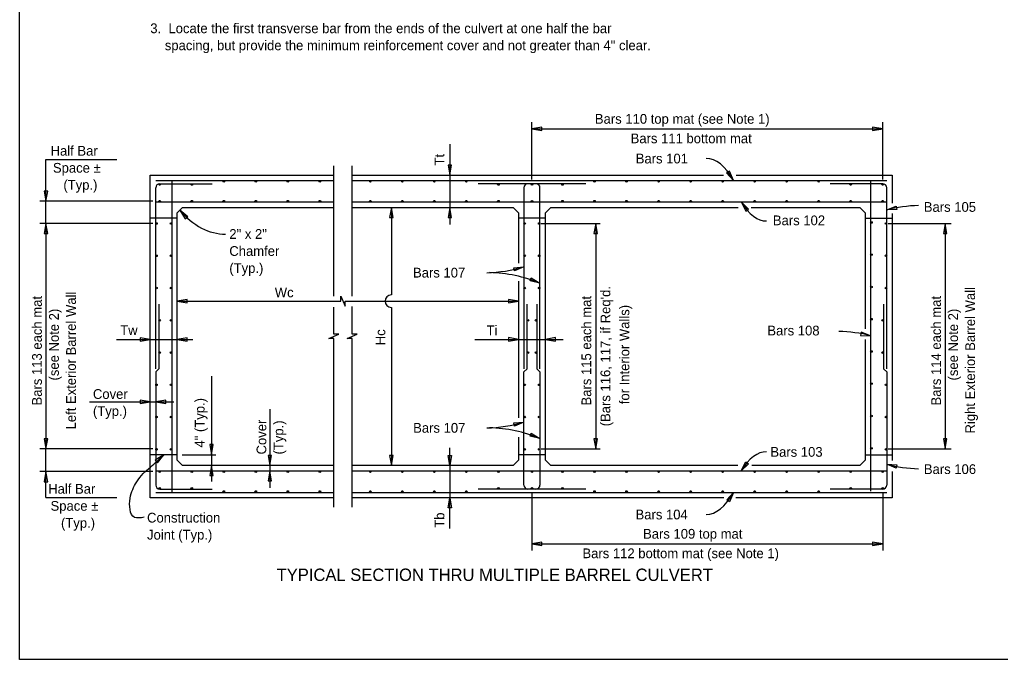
# Model space of a CAD drawing. Extents: x -178 to 179, y -5 to 45.
# Drawn here: x 2.47 to 32.88, y 3.35 to 23.18 of the extents above; entities that cross this region are included whole.
import ezdxf

# ---------------------------------------------------------------- set-up
doc = ezdxf.new("R2010")
doc.units = 0
for name, color, linetype in [('AdhocPoint_dp', 7, 'Continuous'), ('Leader', 7, 'Continuous'), ('PlotBorder_dp', 7, 'Continuous'), ('Rebar', 7, 'Continuous'), ('StrMiscConc', 7, 'Continuous'), ('StrMiscConc_h', 7, 'Continuous'), ('Symbols', 7, 'Continuous')]:
    doc.layers.add(name, color=color, linetype=linetype)

msp = doc.modelspace()

# ---------------------------------------------------------------- linework, layer by layer
at = {"layer": 'Leader'}
msp.add_arc((13.998, 14.455), 0.195, 90, 270, dxfattribs=at)
for centre, major_axis, start_param, end_param in [((23.835, 15.12), (0.076, -3.758), 2.52174, 3.141593), ((25.556, 20.698), (0.076, -3.758), 5.70763, 6.283185), ((25.556, 6.027), (0.076, 3.758), 0, 0.575555), ((23.835, 11.605), (0.076, 3.758), 3.141593, 3.761445)]:
    msp.add_ellipse(centre, major_axis=major_axis, ratio=0.38143, start_param=start_param, end_param=end_param, dxfattribs=at)
msp.add_spline([(6.339, 7.756), (6.039, 7.754), (5.902, 8.348), (6.106, 8.85), (6.303, 9.11), (6.531, 9.312), (6.943, 9.696)], degree=3, dxfattribs=at)
at = {"layer": 'PlotBorder_dp'}
for p, q in [((18.356, 18.228), (18.356, 19.999)), ((18.356, 19.793), (29.231, 19.793)), ((29.231, 18.228), (29.231, 19.999)), ((15.812, 19.32), (15.812, 18.362)), ((3.291, 17.554), (3.291, 18.842)), ((3.291, 18.842), (5.485, 18.842)), ((15.812, 18.362), (15.812, 17.362)), ((6.605, 17.554), (3.097, 17.554)), ((3.291, 16.862), (3.291, 17.554)), ((13.998, 17.362), (13.998, 14.651)), ((15.812, 17.362), (15.812, 16.831)), ((6.605, 16.862), (3.097, 16.862)), ((3.291, 16.862), (3.291, 9.88)), ((18.639, 16.862), (20.469, 16.862)), ((20.332, 16.862), (20.332, 9.88)), ((29.4, 16.862), (31.355, 16.862)), ((31.163, 16.862), (31.163, 9.88)), ((13.998, 14.26), (13.998, 9.362)), ((5.481, 13.264), (6.526, 13.264)), ((6.526, 13.264), (7.36, 13.264)), ((7.36, 13.264), (7.843, 13.264)), ((16.582, 13.271), (17.939, 13.271)), ((17.939, 13.271), (18.772, 13.271)), ((18.772, 13.271), (19.324, 13.271)), ((8.423, 12.13), (8.423, 9.696)), ((4.636, 11.336), (6.526, 11.336)), ((6.526, 11.336), (6.693, 11.336)), ((6.693, 11.336), (7.256, 11.336)), ((10.234, 11.103), (10.234, 9.362)), ((6.605, 9.88), (3.097, 9.88)), ((3.291, 9.171), (3.291, 9.88)), ((15.812, 9.362), (15.812, 9.912)), ((18.639, 9.88), (20.469, 9.88)), ((29.4, 9.88), (31.355, 9.88)), ((7.513, 9.696), (8.555, 9.696)), ((8.423, 9.696), (8.423, 9.362)), ((6.605, 9.171), (3.097, 9.171)), ((3.291, 8.367), (3.291, 9.171)), ((8.423, 9.362), (8.423, 8.868)), ((10.234, 9.362), (10.234, 9.196)), ((10.234, 9.196), (10.234, 8.665)), ((15.812, 9.362), (15.812, 8.362)), ((3.291, 8.367), (5.485, 8.367)), ((15.812, 7.405), (15.812, 8.362)), ((18.356, 8.496), (18.356, 6.726)), ((29.231, 8.496), (29.231, 6.726)), ((18.356, 6.932), (29.231, 6.932))]:
    msp.add_line(p, q, dxfattribs=at)
for points in [[(2.474, 42.838), (63.281, 42.838), (63.281, 3.352), (2.474, 3.352)], [(18.356, 19.793), (18.668, 19.74), (18.668, 19.846)], [(29.231, 19.793), (28.918, 19.846), (28.918, 19.74)], [(15.812, 18.362), (15.865, 18.675), (15.76, 18.675)], [(24.606, 18.196), (24.482, 18.487), (24.392, 18.43)], [(3.291, 17.554), (3.344, 17.867), (3.238, 17.867)], [(13.998, 17.362), (13.945, 17.05), (14.051, 17.05)], [(15.812, 17.362), (15.76, 17.05), (15.865, 17.05)], [(24.84, 17.529), (24.983, 17.247), (25.069, 17.31)], [(29.356, 17.282), (29.649, 17.403), (29.672, 17.299)], [(7.443, 17.279), (7.602, 17.005), (7.684, 17.073)], [(3.291, 16.862), (3.238, 16.55), (3.344, 16.55)], [(20.332, 16.862), (20.28, 16.55), (20.385, 16.55)], [(31.163, 16.862), (31.11, 16.55), (31.216, 16.55)], [(18.106, 15.519), (17.816, 15.39), (17.79, 15.493)], [(18.606, 15.01), (18.297, 15.081), (18.337, 15.179)], [(7.36, 14.455), (7.672, 14.403), (7.672, 14.508)], [(17.939, 14.455), (17.627, 14.508), (17.627, 14.403)], [(28.856, 13.382), (28.561, 13.497), (28.539, 13.393)], [(6.526, 13.264), (6.214, 13.317), (6.214, 13.211)], [(7.36, 13.264), (7.672, 13.211), (7.672, 13.317)], [(17.939, 13.271), (17.627, 13.324), (17.627, 13.218)], [(18.772, 13.271), (19.085, 13.218), (19.085, 13.324)], [(6.526, 11.336), (6.214, 11.389), (6.214, 11.283)], [(6.693, 11.336), (7.005, 11.283), (7.005, 11.389)], [(18.106, 10.709), (17.817, 10.579), (17.79, 10.682)], [(18.606, 10.2), (18.297, 10.27), (18.337, 10.368)], [(3.291, 9.88), (3.344, 10.193), (3.238, 10.193)], [(20.332, 9.88), (20.385, 10.193), (20.28, 10.193)], [(31.163, 9.88), (31.216, 10.193), (31.11, 10.193)], [(8.423, 9.696), (8.476, 10.008), (8.37, 10.008)], [(6.943, 9.696), (6.678, 9.522), (6.751, 9.444)], [(10.234, 9.362), (10.287, 9.675), (10.181, 9.675)], [(13.998, 9.362), (14.051, 9.675), (13.945, 9.675)], [(15.812, 9.362), (15.76, 9.675), (15.865, 9.675)], [(24.84, 9.196), (24.982, 9.479), (25.068, 9.416)], [(3.291, 9.171), (3.238, 8.858), (3.344, 8.858)], [(8.423, 9.362), (8.37, 9.05), (8.476, 9.05)], [(10.234, 9.196), (10.181, 8.883), (10.287, 8.883)], [(29.356, 9.398), (29.672, 9.387), (29.651, 9.283)], [(24.606, 8.529), (24.482, 8.238), (24.393, 8.295)], [(15.812, 8.362), (15.865, 8.05), (15.76, 8.05)], [(18.356, 6.932), (18.668, 6.879), (18.668, 6.984)], [(29.231, 6.932), (28.918, 6.984), (28.918, 6.879)]]:
    msp.add_lwpolyline(points, close=True, dxfattribs=at)
for centre, start, end in [((30.431, 13.079), 91.2114, 104.3468), ((16.864, 19.676), 271.2114, 286.6314), ((16.947, 11.001), 67.5277, 88.7886), ((27.781, 9.179), 75.6532, 88.7886), ((16.864, 14.866), 271.2114, 286.6314), ((16.947, 6.191), 67.5277, 88.7886), ((30.431, 13.601), 255.6532, 268.7886)]:
    msp.add_arc(centre, 4.339, start, end, dxfattribs=at)
msp.add_ellipse((8.83, 20.041), major_axis=(-0.03, 3.508), ratio=0.647453, start_param=2.471513, end_param=3.141593, dxfattribs=at)
at = {"layer": 'Rebar'}
for p, q in [((6.693, 18.196), (12.214, 18.196)), ((6.693, 12.362), (6.693, 17.971)), ((6.818, 18.096), (8.443, 18.096)), ((7.193, 18.196), (7.193, 8.529)), ((12.786, 18.196), (29.356, 18.196)), ((18.481, 18.096), (16.689, 18.096)), ((18.106, 17.971), (18.106, 12.362)), ((20.022, 18.096), (18.231, 18.096)), ((18.606, 12.362), (18.606, 17.971)), ((29.231, 18.096), (27.606, 18.096)), ((28.856, 18.196), (28.856, 8.561)), ((29.356, 12.362), (29.356, 17.971)), ((6.693, 17.529), (12.214, 17.529)), ((12.786, 17.529), (29.356, 17.529)), ((6.793, 14.362), (6.793, 12.362)), ((18.206, 12.362), (18.206, 14.362)), ((18.506, 14.362), (18.506, 12.362)), ((29.256, 14.362), (29.256, 12.362)), ((6.793, 12.362), (6.693, 12.262)), ((6.693, 12.262), (6.693, 8.754)), ((18.106, 12.262), (18.206, 12.362)), ((18.106, 8.754), (18.106, 12.262)), ((18.506, 12.362), (18.606, 12.262)), ((18.606, 12.262), (18.606, 8.754)), ((29.256, 12.362), (29.356, 12.262)), ((29.356, 12.262), (29.356, 8.754)), ((6.693, 9.196), (12.214, 9.196)), ((12.786, 9.196), (29.356, 9.196)), ((6.693, 8.529), (12.214, 8.529)), ((6.818, 8.629), (8.443, 8.629)), ((12.786, 8.529), (29.356, 8.529)), ((18.481, 8.629), (16.689, 8.629)), ((20.022, 8.629), (18.231, 8.629)), ((29.231, 8.629), (27.606, 8.629))]:
    msp.add_line(p, q, dxfattribs=at)
for centre in [(6.818, 18.071), (7.811, 18.071), (8.804, 18.171), (9.796, 18.171), (10.789, 18.171), (11.782, 18.171), (13.347, 18.171), (14.34, 18.171), (15.332, 18.171), (16.325, 18.171), (17.318, 18.071), (18.356, 18.071), (19.303, 18.071), (20.296, 18.171), (21.289, 18.171), (22.282, 18.171), (23.274, 18.171), (24.267, 18.171), (25.26, 18.171), (26.252, 18.171), (27.245, 18.171), (28.238, 18.071), (29.231, 18.071), (6.818, 17.554), (7.811, 17.554), (8.804, 17.554), (9.796, 17.554), (10.789, 17.554), (11.782, 17.554), (13.347, 17.554), (14.34, 17.554), (15.332, 17.554), (16.325, 17.554), (17.318, 17.554), (18.356, 17.554), (19.303, 17.554), (20.296, 17.554), (21.289, 17.554), (22.282, 17.554), (23.274, 17.554), (24.267, 17.554), (25.26, 17.554), (26.252, 17.554), (27.245, 17.554), (28.238, 17.554), (29.231, 17.554), (6.718, 16.862), (7.168, 16.862), (18.131, 16.862), (18.581, 16.862), (28.881, 16.895), (29.331, 16.862), (6.718, 15.862), (7.168, 15.862), (18.131, 15.862), (18.581, 15.862), (28.881, 15.895), (29.331, 15.862), (28.881, 14.895), (6.718, 14.862), (7.168, 14.862), (18.131, 14.862), (18.581, 14.862), (29.331, 14.862), (6.818, 13.862), (7.168, 13.862), (18.231, 13.862), (18.481, 13.862), (28.881, 13.895), (29.231, 13.862), (6.818, 12.862), (7.168, 12.862), (18.231, 12.862), (18.481, 12.862), (28.881, 12.895), (29.231, 12.862), (6.718, 11.862), (7.168, 11.862), (18.131, 11.862), (18.581, 11.862), (28.881, 11.895), (29.331, 11.862), (6.718, 10.862), (7.168, 10.862), (18.131, 10.862), (18.581, 10.862), (28.881, 10.895), (29.331, 10.862), (6.718, 9.862), (7.168, 9.862), (18.131, 9.862), (18.581, 9.862), (28.881, 9.895), (29.331, 9.862), (6.818, 9.171), (7.811, 9.171), (8.804, 9.171), (9.796, 9.171), (10.789, 9.171), (11.782, 9.171), (13.347, 9.171), (14.34, 9.171), (15.332, 9.171), (16.325, 9.171), (17.318, 9.171), (18.356, 9.171), (19.303, 9.171), (20.296, 9.171), (21.289, 9.171), (22.282, 9.171), (23.274, 9.171), (24.267, 9.171), (25.26, 9.171), (26.252, 9.171), (27.245, 9.171), (28.238, 9.171), (29.231, 9.171), (6.818, 8.654), (7.811, 8.654), (8.804, 8.554), (9.796, 8.554), (10.789, 8.554), (11.782, 8.554), (13.347, 8.554), (14.34, 8.554), (15.332, 8.554), (16.325, 8.554), (17.318, 8.654), (18.356, 8.654), (19.303, 8.654), (20.296, 8.554), (21.289, 8.554), (22.282, 8.554), (23.274, 8.554), (24.267, 8.554), (25.26, 8.554), (26.252, 8.554), (27.245, 8.554), (28.238, 8.654), (29.231, 8.654)]:
    msp.add_circle(centre, 0.025, dxfattribs=at)
for centre, start, end in [((6.818, 17.971), 90, 180), ((18.231, 17.971), 90, 180), ((18.481, 17.971), 0, 90), ((29.231, 17.971), 0, 90), ((6.818, 8.754), 180, 270), ((18.231, 8.754), 180, 270), ((18.481, 8.754), 270, 0), ((29.231, 8.754), 270, 0)]:
    msp.add_arc(centre, 0.125, start, end, dxfattribs=at)
at = {"layer": 'StrMiscConc'}
for p, q in [((6.526, 8.362), (6.526, 18.362)), ((6.526, 18.362), (12.214, 18.362)), ((12.786, 18.362), (24.292, 18.362)), ((24.688, 18.362), (29.522, 18.362)), ((29.522, 18.362), (29.522, 17.491)), ((7.36, 17.196), (7.526, 17.362)), ((7.526, 17.362), (12.214, 17.362)), ((12.786, 17.362), (17.772, 17.362)), ((17.772, 17.362), (17.939, 17.196)), ((18.772, 17.196), (18.939, 17.362)), ((18.939, 17.362), (24.748, 17.362)), ((25.151, 17.362), (28.522, 17.362)), ((28.522, 17.362), (28.689, 17.196)), ((7.36, 9.529), (7.36, 17.196)), ((17.939, 17.196), (17.939, 15.634)), ((18.772, 9.529), (18.772, 17.196)), ((28.689, 17.196), (28.689, 13.595)), ((29.522, 17.169), (29.522, 9.521)), ((17.939, 15.077), (17.939, 10.836)), ((28.689, 13.265), (28.689, 9.529)), ((17.939, 10.235), (17.939, 9.529)), ((7.526, 9.362), (7.36, 9.529)), ((17.939, 9.529), (17.772, 9.362)), ((18.939, 9.362), (18.772, 9.529)), ((28.689, 9.529), (28.522, 9.362)), ((12.214, 9.362), (7.526, 9.362)), ((17.772, 9.362), (12.786, 9.362)), ((24.741, 9.362), (18.939, 9.362)), ((28.522, 9.362), (25.172, 9.362)), ((29.522, 9.175), (29.522, 8.362)), ((12.214, 8.362), (6.526, 8.362)), ((24.302, 8.362), (12.786, 8.362)), ((29.522, 8.362), (24.676, 8.362))]:
    msp.add_line(p, q, dxfattribs=at)
at = {"layer": 'StrMiscConc_h'}
for p, q in [((7.36, 17.029), (6.526, 17.029)), ((18.772, 17.029), (17.939, 17.029)), ((28.689, 17.029), (29.522, 17.029)), ((7.36, 9.696), (6.526, 9.696)), ((18.772, 9.696), (17.939, 9.696)), ((28.689, 9.696), (29.522, 9.696))]:
    msp.add_line(p, q, dxfattribs=at)
at = {"layer": 'Symbols'}
for points in [[(12.214, 14.61), (12.214, 18.652)], [(12.786, 14.61), (12.786, 18.652)], [(7.36, 14.455), (12.432, 14.455), (12.432, 14.61), (12.567, 14.3), (12.567, 14.455), (17.939, 14.455)], [(12.214, 8.067), (12.214, 13.295), (12.059, 13.295), (12.369, 13.43), (12.214, 13.43), (12.214, 14.265)], [(12.786, 8.067), (12.786, 13.295), (12.631, 13.295), (12.941, 13.43), (12.786, 13.43), (12.786, 14.285)]]:
    msp.add_lwpolyline(points, dxfattribs=at)

# ---------------------------------------------------------------- texts
at = {"layer": 'AdhocPoint_dp'}
for s, height, p in [('3.  Locate the first transverse bar from the ends of the culvert at one half the bar', 0.3024, (6.526, 22.761)), ('    spacing, but provide the minimum reinforcement cover and not greater than 4" clear.', 0.3024, (6.526, 22.233)), ('Bars 110 top mat (see Note 1)', 0.3024, (20.307, 19.954)), ('Bars 111 bottom mat', 0.3024, (21.416, 19.349)), ('Half Bar', 0.3024, (3.435, 18.965)), ('Bars 101', 0.3024, (21.574, 18.724)), ('Space ±', 0.3024, (3.507, 18.437)), ('(Typ.)', 0.3024, (3.831, 17.909)), ('Bars 105', 0.3024, (30.504, 17.224)), ('Bars 102', 0.3024, (25.825, 16.808)), ('2" x 2"', 0.3024, (8.975, 16.386)), ('Chamfer', 0.3024, (8.975, 15.858)), ('(Typ.)', 0.3024, (8.975, 15.33)), ('Bars 107', 0.3024, (14.67, 15.188)), ('Wc', 0.3024, (10.384, 14.575)), ('Tw', 0.3024, (5.593, 13.406)), ('Ti', 0.3024, (16.949, 13.399)), ('Bars 108', 0.3024, (25.654, 13.393)), ('Cover', 0.3024, (4.747, 11.425)), ('(Typ.)', 0.3024, (4.747, 10.897)), ('Bars 107', 0.3024, (14.674, 10.377)), ('Bars 103', 0.3024, (25.748, 9.632)), ('Bars 106', 0.3024, (30.506, 9.097)), ('Half Bar', 0.3024, (3.361, 8.487)), ('Space ±', 0.3024, (3.433, 7.959)), ('Construction', 0.3024, (6.425, 7.593)), ('Bars 104', 0.3024, (21.568, 7.691)), ('(Typ.)', 0.3024, (3.757, 7.431)), ('Joint (Typ.)', 0.3024, (6.425, 7.065)), ('TYPICAL SECTION THRU MULTIPLE BARREL CULVERT', 0.384, (10.441, 5.782))]:
    msp.add_text(s, height=height, dxfattribs=at).set_placement(p)
for s, rotation, p in [('Tt', 90, (15.641, 18.66)), ('Bars 113 each mat', 90, (3.163, 11.222)), ('Left Exterior Barrel Wall', 90, (4.219, 10.48)), ('Bars 115 each mat', 90, (20.194, 11.222)), ("(Bars 116, 117, if Req'd.", 90, (20.785, 10.576)), ('Bars 114 each mat', 90, (31.036, 11.222)), ('Right Exterior Barrel Wall', 90, (32.092, 10.354)), ('for Interior Walls)', 90, (21.375, 11.261)), ('(see Note 2)', 90, (3.691, 11.996)), ('(see Note 2)', 90, (31.564, 11.996)), ('Hc', 90, (13.81, 13.088)), ('4" (Typ.)', 90, (8.208, 9.917)), ('Cover', 90, (10.122, 9.703)), ('(Typ.)', 90, (10.65, 9.703)), ('Tb', 90, (15.641, 7.432)), ('Bars 109 top mat', 360, (21.801, 7.093)), ('Bars 112 bottom mat (see Note 1)', 360, (19.922, 6.488))]:
    msp.add_text(s, height=0.3024, rotation=rotation, dxfattribs=at).set_placement(p)

doc.saveas('drawing.dxf')
